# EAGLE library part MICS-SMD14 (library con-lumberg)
CONNECTOR
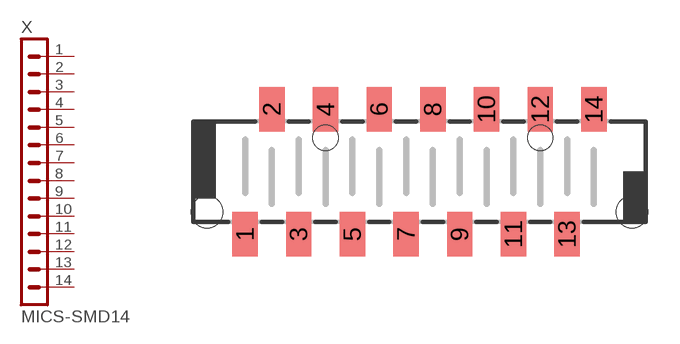
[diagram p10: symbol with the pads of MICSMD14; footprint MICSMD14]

Designator prefix X

## MICS-SMD14 (OC_FARNELL: unknown; OC_NEWARK: unknown)  [MICSMD14]
1  1  pas
2  2  pas
3  3  pas
4  4  pas
5  5  pas
6  6  pas
7  7  pas
8  8  pas
9  9  pas
10  10  pas
11  11  pas
12  12  pas
13  13  pas
14  14  pas

## Footprint MICSMD14 (pad centres in mm)
CONNECTOR
smd 1.2 x 2.1: 1 -8.255,-2.959; 2 -6.985,2.959; 3 -5.715,-2.959; 4 -4.445,2.959; 5 -3.175,-2.959; 6 -1.905,2.959; 7 -0.635,-2.959; 8 0.635,2.959; 9 1.905,-2.959; 10 3.175,2.959; 11 4.445,-2.959; 12 5.715,2.959; 13 6.985,-2.959; 14 8.255,2.959
hole 1.5 at 10.055,-1.912
hole 1.5 at -10.055,-1.912
hole 1.2 at -4.445,1.6
hole 1.2 at 5.715,1.6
